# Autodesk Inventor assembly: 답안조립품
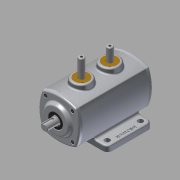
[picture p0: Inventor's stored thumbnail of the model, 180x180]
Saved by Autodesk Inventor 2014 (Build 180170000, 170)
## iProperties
Created: 2015-07
Part Number: 답안조립품
Document SubType Name: Assembly
Designer: Administrator
Mass: 2515.1 g
Surface Area: 1894.53 cm^2
Volume: 719.238 cm^3
Density: 3.4969 g/cm^3
Author: Administrator
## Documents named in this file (12)
- C:\Users\Administrator\Desktop\350727V1004\답안조립품.iam
- C:\Users\Administrator\Desktop\350727V1004\본체.ipt
- C:\Users\Administrator\Desktop\350727V1004\앞커버.ipt
- C:\Users\Administrator\Desktop\350727V1004\베어링 6203.ipt
- C:\Users\Administrator\Desktop\350727V1004\오일실.ipt
- C:\Users\Administrator\Desktop\350727V1004\M4-소켓머리.ipt
- C:\Users\Administrator\Desktop\350727V1004\뒷커버.ipt
- C:\Users\Administrator\Desktop\350727V1004\부시.ipt
- C:\Users\Administrator\Desktop\350727V1004\스프링.ipt
- C:\Users\Administrator\Desktop\350727V1004\스프링1.ipt
- C:\Users\Administrator\Desktop\350727V1004\슬라이더.ipt
- C:\Users\Administrator\Desktop\350727V1004\축.ipt
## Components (11 placed, 3 different names)
1. 7-베어링 6203:1 — 각도:1
2. 8-오일실:1
3. 7-베어링 6203:2 — 각도:2
4. 9-M4-소켓머리:1
5. 9-M4-소켓머리:2
6. 9-M4-소켓머리:3
7. 9-M4-소켓머리:4
8. 9-M4-소켓머리:5
9. 9-M4-소켓머리:6
10. 9-M4-소켓머리:7
11. 9-M4-소켓머리:8
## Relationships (2: Angle 2)
- 각도:1 [Angle]: 7-베어링 6203:1
- 각도:2 [Angle]: 7-베어링 6203:2
